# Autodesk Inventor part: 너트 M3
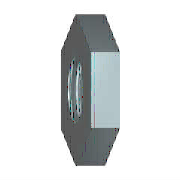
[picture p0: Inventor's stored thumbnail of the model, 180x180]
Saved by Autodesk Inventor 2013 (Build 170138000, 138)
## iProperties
Created: 2012-02
Part Number: 너트 M3
Material: 강철, 연강
Description: 6각 너트 및 6각 가는 너트 - 모따기 안된
Document SubType Name: Modeling
Standard: KS B 1012
Designer: mduedu
Standards Organization: KS
Language: ko-KR
Size Designation: B  M 3
Categories: <MemberInstance><Categories><Category DisplayName="조임쇠" InternalName="e4da775c-781d-43d5-af7c-5136215cf5a6" Mnemonic="FSTN"><Category DisplayName="너트" InternalN
Density: 7.86 g/cm^3
Mass: 0.300693 g
Surface Area: 0.894003 cm^2
Volume: 0.0382562 cm^3
IsCustomPart: 0
Author: mduedu
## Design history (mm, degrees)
sketch "스케치1"
  geometry: L1 (1.588, -2.75)-(-1.588, -2.75); L2 (-1.588, -2.75)-(-3.175, 0); L3 (-3.175, 0)-(-1.588, 2.75); L4 (-1.588, 2.75)-(1.588, 2.75); L5 (1.588, 2.75)-(3.175, 0); L6 (3.175, 0)-(1.588, -2.75); 2 further points
  constraints: 12 end point, 1 coincident, 1 horizontal, 11 other
  dimensions: "d0" = 6.35085 distance of L5.end L2.end (= 1.1547 x SW)
extrude "본체" new body sketch "스케치1" distance "d1" = 1.8 (= KOH); taper "d2" = 0 deg
sketch "스케치2"
  geometry: 1 further point
hole "스레드" sketch "스케치2" diameter "d3" = 2.459; stored, may be unused: countersink angle "d7" = 82 deg, drill point angle "d9" = 118 deg; dims "d4" = 6, "d5" = 4, "d6" = 2, "d8" = 8
workaxis "Work Axis1"
workplane "Work Plane1"
body "Solid1"
chamfer "모따기2" distance "d12" = 0.27063 (= -0.5 x GD1 + 0.5 x NND); stored, may be unused: angle "d13" = 30 deg, second distance "d19" = 0.27063 (= -0.5 x GD1 + 0.5 x NND)
chamfer "모따기1" distance "d10" = 0.27063 (= -0.5 x GD1 + 0.5 x NND); stored, may be unused: angle "d11" = 30 deg, second distance "d18" = 0.27063 (= -0.5 x GD1 + 0.5 x NND)
other parameters: "NND" = 3 [user parameter; used in 4 equation terms], "KOH" = 1.8 [user parameter; used in 1 equation term], "SW" = 5.5 [user parameter; used in 2 equation terms], "GD1" = 2.45873 (computed from THREADDIA, PTC, TOA) [user parameter; used in 4 equation terms], "d15" = 0, "d17" = 0, "d20" = 0, "d21" = 0, "GUL" = 0.27063 (= 0.541266 x PTC) [user parameter], "THREADDIA" = 3 [user parameter; used in 1 equation term], "TOA" = 30 deg [user parameter; used in 1 equation term], "PTC" = 0.5 [user parameter; used in 4 equation terms], "E0" = 6.3525 (= 1.155 x SW) [user parameter], "GAL" = 0.27063 (= 0.541266 x PTC) [user parameter]
